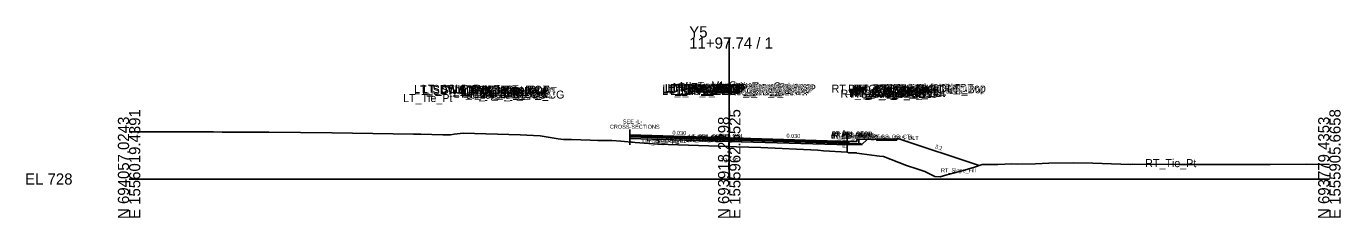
# Model space of a CAD drawing. Extents: x -26 to 4229, y -10 to 9523.
# Drawn here: x -25.7 to 302.8, y 3490.3 to 3538.2 of the extents above; entities that cross this region are included whole.
import ezdxf

# ---------------------------------------------------------------- set-up
doc = ezdxf.new("R2010")
doc.units = 0
for name, color, linetype in [('Default', 7, 'Continuous'), ('Exist Cross Section Cell', 7, 'Continuous'), ('Exist XS Center Line Elevation Label', 7, 'Continuous'), ('Exist XS Ground Line', 7, 'Continuous'), ('Old_Level_63', 7, 'Continuous'), ('Prop CMT Conc Surface', 7, 'Continuous'), ('Prop CMT Concrete Structures', 7, 'Continuous'), ('Prop CMT Pvmt Course 1', 7, 'Continuous'), ('Prop CMT Pvmt Course 1 CG', 7, 'Continuous'), ('Prop CMT Pvmt Course 2', 7, 'Continuous'), ('Prop CMT Pvmt Course 3', 7, 'Continuous'), ('Prop CMT Pvmt Surface', 7, 'Continuous'), ('Prop CMT Pvmt Surface Shoulder', 7, 'Continuous'), ('Prop CMT Shld Paved Course 1', 7, 'Continuous'), ('Prop CMT Shld Paved Course 2', 7, 'Continuous'), ('Prop CMT Shld Paved Course 3', 7, 'Continuous'), ('Prop CMT Slope Grass', 7, 'Continuous'), ('Prop CMT Subgrade Earthwork', 7, 'Continuous'), ('Prop XS Earthwork Shape', 7, 'Continuous'), ('Prop XS Label Text', 7, 'Continuous'), ('Prop XSC Text', 7, 'Continuous'), ('Scratch_Level_1', 7, 'Continuous')]:
    doc.layers.add(name, color=color, linetype=linetype)

msp = doc.modelspace()

# ---------------------------------------------------------------- linework, layer by layer
at = {"layer": 'Exist Cross Section Cell'}
for p, q in [((150, 3500), (150, 3535.43)), ((0, 3500), (150, 3500)), ((150, 3500), (300, 3500))]:
    msp.add_line(p, q, dxfattribs=at)
at = {"layer": 'Exist XS Ground Line'}
msp.add_lwpolyline([(0, 3511.81), (19.63, 3511.78), (20.47, 3511.78), (21.11, 3511.78), (23.3, 3511.75), (27.11, 3511.73), (34.94, 3511.69), (50.77, 3511.53), (71.07, 3511.22), (71.71, 3511.21), (72.91, 3511.19), (78.46, 3511.09), (80.36, 3511.07), (81.28, 3511.19), (83.54, 3511.46), (97.79, 3511.05), (102.74, 3510.79), (107.26, 3510.03), (108.6, 3509.87), (109.92, 3509.87), (110.6, 3509.86), (115.21, 3509.69), (117.13, 3509.67), (120.62, 3509.65), (122.91, 3509.48), (126.47, 3509.18), (129.89, 3508.91), (132.14, 3508.74), (150, 3508.15), (151.79, 3508.09), (154.93, 3508), (157.87, 3507.88), (172.15, 3507.19), (173.59, 3507.07), (179.49, 3506.69), (179.91, 3506.57), (181.8, 3506.52), (181.92, 3506.51), (185.66, 3505.93), (187.57, 3505.71), (188.58, 3505.6), (194.3, 3503.4), (196.87, 3502.58), (198.91, 3501.88), (201.4, 3500.6), (202.69, 3500.52), (204.4, 3501.04), (205.04, 3501.19), (208.8, 3502.21), (211.34, 3502.99), (213.19, 3503.64), (217.18, 3503.62), (220.65, 3503.76), (221.94, 3503.71), (226.55, 3503.79), (229.9, 3503.94), (236.1, 3504.03), (240.9, 3503.99), (250.25, 3503.67), (250.84, 3503.69), (262.54, 3503.65), (263.87, 3503.63), (264.77, 3503.64), (285.17, 3503.65), (294.18, 3503.68), (300, 3503.67)], dxfattribs=at)
at = {"layer": 'Old_Level_63'}
msp.add_line((125.15, 3512.43), (125.15, 3508.55), dxfattribs=at)
at = {"layer": 'Prop CMT Conc Surface'}
msp.add_lwpolyline([(179.88, 3509.4), (181.88, 3509.38)], dxfattribs=at)
at = {"layer": 'Prop CMT Concrete Structures'}
for points in [[(179.88, 3509.4), (181.88, 3509.38), (181.88, 3509.88), (182.38, 3509.88)], [(182.38, 3509.88), (182.38, 3508.89), (179.88, 3508.82)], [(179.88, 3508.82), (179.88, 3509.4)], [(191.87, 3510.08), (186.87, 3509.98)], [(186.87, 3509.98), (186.87, 3509.64)], [(186.87, 3509.64), (191.87, 3509.74)], [(191.87, 3509.74), (191.87, 3510.08)]]:
    msp.add_lwpolyline(points, dxfattribs=at)
at = {"layer": 'Prop CMT Pvmt Course 1'}
for points in [[(150, 3510.3), (125.15, 3511.05)], [(125.15, 3511.05), (125.15, 3510.8)], [(125.15, 3510.8), (150, 3510.05)], [(150, 3510.05), (150, 3510.3)], [(150, 3510.3), (179.88, 3509.4)], [(150, 3510.05), (150, 3510.3)], [(179.88, 3509.15), (150, 3510.05)], [(179.88, 3509.4), (179.88, 3509.15)]]:
    msp.add_lwpolyline(points, dxfattribs=at)
at = {"layer": 'Prop CMT Pvmt Course 1 CG'}
for points in [[(179.88, 3508.82), (182.88, 3508.9), (183.16, 3508.62)], [(183.16, 3508.62), (179.88, 3508.53)]]:
    msp.add_lwpolyline(points, dxfattribs=at)
at = {"layer": 'Prop CMT Pvmt Course 2'}
for points in [[(150, 3510.05), (125.15, 3510.8)], [(125.15, 3510.8), (125.15, 3510.55)], [(125.15, 3510.55), (150, 3509.8)], [(150, 3509.8), (150, 3510.05)], [(150, 3509.8), (150, 3510.05)], [(150, 3510.05), (179.88, 3509.15)], [(179.88, 3508.9), (150, 3509.8)], [(179.88, 3509.15), (179.88, 3508.9)]]:
    msp.add_lwpolyline(points, dxfattribs=at)
at = {"layer": 'Prop CMT Pvmt Course 3'}
for points in [[(150, 3509.8), (125.15, 3510.55)], [(125.15, 3510.55), (125.15, 3510.17)], [(125.15, 3510.17), (150, 3509.43)], [(150, 3509.43), (150, 3509.8)], [(150, 3509.8), (179.88, 3508.9)], [(150, 3509.43), (150, 3509.8)], [(179.88, 3508.53), (150, 3509.43)], [(179.88, 3508.9), (179.88, 3508.53)], [(179.88, 3508.82), (179.88, 3508.53)]]:
    msp.add_lwpolyline(points, dxfattribs=at)
at = {"layer": 'Prop CMT Pvmt Surface'}
msp.add_line((179.88, 3509.4), (179.88, 3509.15), dxfattribs=at)
for points in [[(150, 3510.3), (125.15, 3511.05)], [(150, 3510.3), (179.88, 3509.4)]]:
    msp.add_lwpolyline(points, dxfattribs=at)
at = {"layer": 'Prop CMT Pvmt Surface Shoulder'}
for points in [[(125.15, 3511.05), (125.15, 3511.05)], [(179.88, 3509.4), (179.88, 3509.4)]]:
    msp.add_lwpolyline(points, dxfattribs=at)
at = {"layer": 'Prop CMT Shld Paved Course 1'}
for points in [[(125.15, 3511.05), (125.15, 3511.05)], [(125.15, 3510.8), (125.15, 3511.05)], [(179.88, 3509.4), (179.88, 3509.4)], [(179.88, 3509.15), (179.88, 3509.4)]]:
    msp.add_lwpolyline(points, dxfattribs=at)
at = {"layer": 'Prop CMT Shld Paved Course 2'}
for points in [[(125.15, 3510.55), (125.15, 3510.8)], [(179.88, 3508.9), (179.88, 3509.15)]]:
    msp.add_lwpolyline(points, dxfattribs=at)
at = {"layer": 'Prop CMT Shld Paved Course 3'}
for points in [[(125.15, 3510.17), (125.15, 3510.55)], [(179.88, 3508.53), (179.88, 3508.9)]]:
    msp.add_lwpolyline(points, dxfattribs=at)
at = {"layer": 'Prop CMT Slope Grass'}
for points in [[(182.38, 3509.88), (192.37, 3510.08)], [(192.37, 3510.08), (212.46, 3503.38)]]:
    msp.add_lwpolyline(points, dxfattribs=at)
at = {"layer": 'Prop CMT Subgrade Earthwork'}
for p, q in [((125.15, 3509.29), (125.15, 3511.05)), ((183.16, 3508.62), (184.46, 3509.92))]:
    msp.add_line(p, q, dxfattribs=at)
for points in [[(150, 3509.43), (125.15, 3510.17)], [(150, 3509.43), (179.88, 3508.53)], [(179.88, 3508.53), (183.16, 3508.62)]]:
    msp.add_lwpolyline(points, dxfattribs=at)
at = {"layer": 'Prop XS Earthwork Shape'}
msp.add_lwpolyline([(188.58, 3505.6), (194.3, 3503.4), (196.87, 3502.58), (198.91, 3501.88), (201.4, 3500.6), (202.69, 3500.52), (204.4, 3501.04), (205.04, 3501.19), (208.8, 3502.21), (211.34, 3502.99), (212.46, 3503.38), (192.37, 3510.08), (191.87, 3510.08), (191.87, 3509.74), (186.87, 3509.64), (186.87, 3509.98), (184.47, 3509.92), (183.16, 3508.62), (179.88, 3508.53), (150, 3509.43), (125.15, 3510.17), (125.15, 3509.29), (126.47, 3509.18), (129.89, 3508.91), (132.14, 3508.74), (150, 3508.15), (151.79, 3508.09), (154.93, 3508), (157.87, 3507.88), (172.15, 3507.19), (173.59, 3507.07), (179.49, 3506.69), (179.91, 3506.57), (181.8, 3506.52), (181.92, 3506.51), (185.66, 3505.93), (187.57, 3505.71)], close=True, dxfattribs=at)
at = {"layer": 'Prop XS Label Text'}
msp.add_line((179.49, 3511.69), (179.49, 3506.69), dxfattribs=at)

# ---------------------------------------------------------------- texts
at = {"layer": 'Default'}
for s, height, p in [('LT_SDWK_Out_Top', 2, (71.24, 3521.56)), ('LT_SDWK_Out_Bot', 2, (71.27, 3521.22)), ('LT_CSLP_Pnt', 2, (73.17, 3521.58)), ('LT_Sub_Trench_Out_DLT', 2, (73.49, 3521.38)), ('LT_SDWK_In_Top', 2, (77.86, 3521.46)), ('LT_SDWK_In_Bot', 2, (77.89, 3521.12)), ('LT_CG1_Shelf_Out', 2, (81.05, 3520.32)), ('LT_CG_Top_Face', 2, (82.76, 3521.34)), ('LT_CG_Top_BOC', 2, (83.28, 3521.34)), ('LT_CG_Bot_BOC', 2, (83.31, 3520.33)), ('LT_CG_Top_Gut', 2, (83.74, 3520.84)), ('LT_Sub_OEOP', 2, (84.36, 3520.06)), ('LT_Sub_OEOT_CG', 2, (84.87, 3520.13)), ('LT_CG_Bot_IE', 2, (87.41, 3520.38)), ('LT_Sub_OEOT', 2, (87.58, 3520.09)), ('LT_PV2_OEOT', 2, (87.67, 3520.71)), ('LT_PV3_OEOT', 2, (87.67, 3520.46)), ('LT_PV1_OEOT', 2, (88.24, 3520.96)), ('LT_Sub_OEEOP', 2, (133.24, 3521.02)), ('LT_PV2_OEEOP', 2, (133.34, 3521.64)), ('LT_PV3_OEEOP', 2, (133.34, 3521.39)), ('LT_PV1_OEEOP', 2, (133.9, 3521.77)), ('LT_PV2_IEEOP', 2, (133.98, 3521.64)), ('LT_PV1_IEEOP', 2, (134.55, 3521.77)), ('LT_PV2_PGL1', 2, (134.91, 3521.64)), ('LT_PV3_PGL1', 2, (134.91, 3521.39)), ('LT_PV2_PGL', 2, (135.24, 3521.64)), ('LT_PV4_PGL', 2, (135.24, 3521.02)), ('LT_PV1_PGL', 2, (135.81, 3521.89)), ('MI_Face In', 2, (135.93, 3522.06)), ('MI_Bot In', 2, (136.91, 3521.89)), ('MI_Top In', 2, (137.64, 3522.31)), ('MI_Crown', 2, (145.46, 3522.46)), ('RT_Sub_OEEOP', 2, (149.92, 3520.92)), ('RT_PV2_OEEOP', 2, (150.01, 3521.55)), ('RT_PV3_OEEOP', 2, (150.01, 3521.3)), ('RT_PV1_OEEOP', 2, (150.58, 3521.67)), ('RT_PV2_IEEOP', 2, (150.66, 3521.55)), ('MI_Face Out', 2, (151.01, 3521.96)), ('MI_Top Out', 2, (151.22, 3522.21)), ('RT_PV1_IEEOP', 2, (151.22, 3521.67)), ('RT_PV2_PGL1', 2, (151.58, 3521.55)), ('RT_PV3_PGL1', 2, (151.58, 3521.3)), ('RT_PV2_PGL', 2, (151.92, 3521.55)), ('RT_PV4_PGL', 2, (151.92, 3520.92)), ('MI_Bot Out', 2, (152.01, 3521.8)), ('RT_PV1_PGL', 2, (152.48, 3521.8)), ('RT_Sub_Trench_Out_DLT', 2, (175.59, 3521.62)), ('RT_Sub_OEOT_CG', 2, (177.82, 3520.37)), ('RT_CG_Top_Face', 2, (179.71, 3521.58)), ('RT_CG1_Shelf_Out', 2, (180, 3520.56)), ('RT_CG_Bot_IE', 2, (180.37, 3520.62)), ('RT_Sub_OEOT', 2, (180.53, 3520.33)), ('RT_PV2_OEOT', 2, (180.63, 3520.95)), ('RT_PV3_OEOT', 2, (180.63, 3520.7)), ('RT_CG_Top_Gut', 2, (180.69, 3521.08)), ('RT_PV1_OEOT', 2, (181.19, 3521.2)), ('RT_CG_Top_BOC', 2, (181.24, 3521.58)), ('RT_CG_Bot_BOC', 2, (181.27, 3520.57)), ('RT_Sub_OEOP', 2, (183.82, 3520.3)), ('RT_SDWK_In_Top', 2, (185.81, 3521.7)), ('RT_SDWK_In_Bot', 2, (185.84, 3521.36)), ('RT_SDWK_Out_Top', 2, (189.19, 3521.8)), ('RT_SDWK_Out_Bot', 2, (189.22, 3521.46)), ('RT_Shld_O', 2, (195.54, 3521.78)), ('CSLP_Pnt', 2, (197.87, 3521.82)), ('LT_Tie_Pt', 2, (68.48, 3519.26)), ('RT_Tie_Pt', 2, (253.97, 3502.97)), ('-', 0.0001, (0, 3500)), ('-', 0.0001, (0, 3500)), ('-', 0.0001, (0, 3500)), ('-', 0.0001, (0, 3500)), ('-', 0.0001, (0, 3500)), ('-', 0.0001, (0, 3500)), ('-', 0.0001, (0, 3500)), ('-', 0.0001, (0, 3500)), ('-', 0.0001, (0, 3500)), ('-', 0.0001, (0, 3500))]:
    msp.add_text(s, height=height, dxfattribs=at).set_placement(p)
at = {"layer": 'Exist Cross Section Cell'}
for s, p in [('Y5', (140, 3535.43)), ('11+97.74 / 1', (140, 3532.63)), ('EL 728', (-26, 3498.6))]:
    msp.add_text(s, height=2.8, dxfattribs=at).set_placement(p)
for s, p in [('N 694057.0243', (0, 3490)), ('E 1556019.4391', (2.8, 3490)), ('N 693918.2298', (150, 3490)), ('E 1555962.5525', (152.8, 3490)), ('N 693779.4353', (300, 3490)), ('E 1555905.6658', (302.8, 3490))]:
    msp.add_text(s, height=2.8, rotation=90, dxfattribs=at).set_placement(p)
at = {"layer": 'Exist XS Center Line Elevation Label'}
msp.add_text('736.15', height=1, dxfattribs=at).set_placement((147.99, 3504.15))
at = {"layer": 'Prop XS Label Text'}
msp.add_text('E. EOP', height=1, rotation=90, dxfattribs=at).set_placement((179.39, 3507.71))
at = {"layer": 'Prop XSC Text'}
for s, p in [('CROSS-SECTIONS', (120.18, 3512.58)), ('SEE -L-', (123.41, 3513.89))]:
    msp.add_text(s, height=1, dxfattribs=at).set_placement(p)
for s, rotation, p in [('0.030', 358.2816, (135.79, 3511.1)), ('0.030', 358.2816, (164.3, 3510.34)), ('3:1', 341.5651, (201.34, 3507.72))]:
    msp.add_text(s, height=1, rotation=rotation, dxfattribs=at).set_placement(p)
at = {"layer": 'Scratch_Level_1'}
for s, p in [('LT_Sub_OSS_DLT', (128.27, 3509.11)), ('LT_Slope_Fill', (128.91, 3508.73)), ('LT_GS_OS_CTL', (129.46, 3509.39)), ('LT_Sub_Trench_Out', (136.72, 3509.29)), ('LT_PS3_Shelf_Out', (137.65, 3509.67)), ('LT_PS3_OEOP', (139.28, 3509.68)), ('LT_PS2_OEOP', (139.53, 3509.94)), ('LT_PV2_OEOT', (139.75, 3509.94)), ('LT_PV3_OEOT', (139.75, 3509.69)), ('LT_Sub_OEOT', (139.77, 3509.32)), ('LT_PV1_OEOT', (139.87, 3510.19)), ('LT_PS1_OEOP', (139.91, 3510.19)), ('Sub_PGL', (147.37, 3509.43)), ('PV2_PGL', (147.35, 3510.06)), ('PV3_PGL', (147.35, 3509.81)), ('PV1_PGL', (147.47, 3510.31)), ('RT_Sub_Trench_Out', (175.32, 3510.01)), ('RT_PS3_Shelf_Out', (175.48, 3510.39)), ('RT_PV2_OEOT', (175.56, 3510.66)), ('RT_PV3_OEOT', (175.56, 3510.41)), ('RT_Sub_OEOT', (175.59, 3510.03)), ('RT_PV1_OEOT', (175.68, 3510.91)), ('RT_PS1_OEOP', (175.72, 3510.91)), ('RT_PS2_OEOP', (175.86, 3510.65)), ('RT_PS3_OEOP', (176.11, 3510.4)), ('RT_Sub_OSS_DLT', (185.24, 3509.82)), ('RT_GS_OS_CTL', (185.28, 3510.11)), ('RT_Slope_Fill', (202.94, 3501.67))]:
    msp.add_text(s, height=1, rotation=359.8763, dxfattribs=at).set_placement(p)

doc.saveas('drawing.dxf')
